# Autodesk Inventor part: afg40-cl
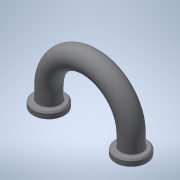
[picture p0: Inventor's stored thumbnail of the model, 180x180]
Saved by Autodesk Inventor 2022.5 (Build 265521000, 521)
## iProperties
Created: 2016-12
Part Number: afg40-cl
Material: 一般
Document SubType Name: Modeling
Designer: imaocorp
Density: 1 g/cm^3
Appearance: 既定
Author: imaocorp
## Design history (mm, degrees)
node "afg40-cl.x_t1"
node "afg40-cl"
node "Base1"
